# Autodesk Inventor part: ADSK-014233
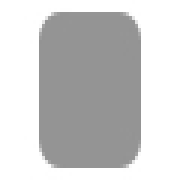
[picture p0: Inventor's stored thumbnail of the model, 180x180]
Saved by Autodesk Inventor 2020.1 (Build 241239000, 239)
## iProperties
Created: 2019-01
Part Number: ADSK-014233
Material: Stahl, weich
Document SubType Name: Modeling
Designer: lutzd
Language: de-DE
Size Designation: 5 x 39,384472 x 39,384472
Categories: <MemberInstance><Categories><Category DisplayName="Sonstige Bauteile" InternalName="5aa15e00-363f-49f2-933f-16f664388e3f" Mnemonic="OTHER"><Category DisplayName
Mass: 60.0398 g
Surface Area: 38.0412 cm^2
Volume: 7.64838 cm^3
Density: 7.85 g/cm^3
Appearance: Halbpoliert
IsCustomPart: 1
Title: Endcap
Author: lutzd
Revision Number: -
Dimensions: 39,4x39,4x5 mm
Mass: 0,06 kg
DocNumber: ADSK-014233
Folder: 01 - Themengebiete\Simplification\01 - Packaging machine\ADSK-014200\Frame\
VDS_Category: 3D Komponenten
VDS_NumSchm: Autodesk
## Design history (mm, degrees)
sketch "Sketch1"
  geometry: L1 (0, 20.175)-(0, -21.446); L2 (-20.203, 0)-(20.169, 0); L3 (-19.692, 19.692)-(19.692, 19.692); L4 (19.692, 19.692)-(19.692, -19.692); L5 (19.692, -19.692)-(-19.692, -19.692); L6 (-19.692, -19.692)-(-19.692, 19.692); 1 further point
  constraints: 12 end point, 2 horizontal, 2 parallel, 2 point on line, 1 perpendicular, 1 vertical
  dimensions: "d0" = 39.38447 distance between parallel lines of L5 L3 (= height); "d1" = 19.69224 distance between parallel lines of L2 L3 (= 0.5 x height); "d2" = 39.38447 distance between parallel lines of L6 L4 (= width); "d3" = 19.69224 distance between parallel lines of L6 L1 (= 0.5 x width)
extrude "Extrusion1" new body sketch "Sketch1" distance "d4" = 5 (= thickness); taper "d5" = 0 deg
fillet "Fillet1" dims "d6" = 5 (= fillet), "d7" = 0, "fillet" = 5 [user parameter; used in 1 equation term]
chamfer "Chamfer1" distance "d8" = 0 (computed from chamfer); stored, may be unused: second distance "d9" = 2, angle "d10" = 45 deg; dims "d11" = 0, "chamfer" = 0 [user parameter; used in 1 equation term]
body "Solid1"
other parameters: "thickness" = 5 [user parameter; used in 1 equation term], "width" = 39.38447 [user parameter; used in 2 equation terms], "height" = 39.38447 [user parameter; used in 2 equation terms]
